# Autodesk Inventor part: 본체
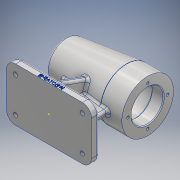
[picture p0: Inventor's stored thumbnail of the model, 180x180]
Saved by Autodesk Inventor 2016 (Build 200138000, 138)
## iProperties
Created: 2018-09
Part Number: 본체
Material: 알루미늄 6061
Document SubType Name: Modeling
Designer: CAMTIC
Density: 2.7 g/cm^3
Appearance: 알루미늄 - 평지
Author: CAMTIC
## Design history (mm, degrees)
sketch "스케치1"
  geometry: L1 (56, 35)-(-56, 35); L2 (-56, 35)-(-56, -35); L3 (-56, -35)-(56, -35); L4 (56, -35)-(56, 35); L5 (56, 35)-(-56, -35); L6 (-56, 35)-(56, -35); 1 further point
  constraints: 12 end point, 2 midpoint, 2 parallel, 1 horizontal, 1 perpendicular
  dimensions: "d0" = 112 distance of L2.end L3.end; "d1" = 70 distance of L1.end L2.end
extrude "돌출1" new body sketch "스케치1" distance "d2" = 10; taper "d3" = 0 deg
sketch "스케치2"
  geometry: L1 (0, 129.6)-(0, -21.6) reference; L2 (-105.225, 0)-(138.871, 0) reference; L3 (-70.354, 74)-(64.903, 74); L4 (-52.27, 98.144)-(28, 108); L5 (28, 108)-(56, 108); L6 (56, 108)-(56, 74); L7 (56, 74)-(-56, 74); L8 (104, 74)-(-56, 74); L9 (24, 74)-(-56, 74); A1 r 80 centre (24, 74) between (-52.27, 98.144) and (-56, 74); 1 further point
  constraints: 14 end point, 2 collinear, 2 horizontal, 2 perpendicular, 2 point on circle, 1 centre point
  dimensions: "d4" = 74 distance between parallel lines of L2 L3; "d5" = 28 distance from line of L4.end L6; "d6" = 34 distance of L5.end L6.end; "d7" = 7 deg angle of L4 L5; "d10" = 56 distance between parallel lines of L1 L6; "d13" = 112 distance of L7.end L6.end; "d14" = 80 radius of A1
revolve "회전1" sketch "스케치2" stored, may be unused: angle "d18" = 90 deg
sketch "스케치3"
  geometry: L1 (-52.27, 98.144)-(28, 108) reference; L2 (56, 40)-(56, 108) reference; L3 (28, 108)-(56, 108) reference; L4 (-52.27, 49.856)-(28, 40) reference; L5 (28, 40)-(56, 40) reference; L6 (0, 129.6)-(0, -21.6) reference; L7 (-78.4, 0)-(78.4, 0) reference; L8 (-85.36, 74)-(107.165, 74); L9 (-50, 74)-(-50, 84.5); L10 (-50, 84.5)-(-47, 84.5); L11 (-47, 84.5)-(-47, 90); L12 (-47, 90)-(-43, 90); L13 (-43, 90)-(-43, 91.5); L14 (-43, 91.5)-(-25, 91.5); L15 (-25, 91.5)-(-25, 95); L16 (-25, 95)-(-13, 95); L17 (-13, 95)-(-13, 98); L18 (-13, 98)-(41, 98); L19 (41, 98)-(41, 95); L20 (41, 95)-(56, 95); L21 (56, 95)-(56, 74); L22 (56, 74)-(-50, 74); A1 r 80 centre (24, 74) between (-52.27, 98.144) and (-52.27, 49.856) reference; 1 further point
  constraints: 30 end point, 13 perpendicular, 2 collinear, 1 horizontal, 1 vertical
  dimensions: "d19" = 74 distance between parallel lines of L7 L8; "d20" = 15 distance of L19.end L20.end; "d21" = 54 distance of L17.end L18.end; "d22" = 12 distance of L15.end L16.end; "d23" = 18 distance of L13.end L14.end; "d24" = 4 distance of L11.end L12.end; "d25" = 3 distance of L9.end L10.end; "d26" = 10.5 distance of L9.start L9.end; "d27" = 16 distance between parallel lines of L22 L12; "d28" = 17.5 distance between parallel lines of L22 L14; "d29" = 21 distance between parallel lines of L22 L16; "d30" = 24 distance between parallel lines of L8 L18; "d31" = 21 distance between parallel lines of L8 L20
revolve "회전2" sketch "스케치3" stored, may be unused: angle "d32" = 90 deg
fillet "모깎기1" dims "d33" = 0.3
fillet "모깎기2" dims "d34" = 3
chamfer "모따기1" distance "d35" = 1; stored, may be unused: second distance "d36" = 2, angle "d37" = 45 deg
fillet "모깎기3" dims "d38" = 3
fillet "모깎기4" dims "d39" = 3
sketch "스케치4"
  geometry: L1 (-50.331, 49.618)-(27.818, 40.022) reference; L2 (-56, 10)-(56, 10) reference; L3 (-50.331, 49.618)-(27.818, 40.022) reference; L4 (28.183, 40)-(56, 40) reference; L5 (0, 129.6)-(0, -21.6) reference; L6 (-78.4, 0)-(78.4, 0) reference; L7 (-38, 10)-(-27.899, 47.699); L8 (-27.899, 47.699)-(38, 47.699); L9 (38, 47.699)-(38, 10); L10 (38, 10)-(-38, 10); L11 (-56, 0)-(-56, 10) reference; L12 (56, 0)-(56, 10) reference; A1 r 3 centre (28.183, 43) between (27.818, 40.022) and (28.183, 40) reference; 1 further point
  constraints: 8 end point, 1 collinear, 1 horizontal, 1 parallel, 1 vertical
  dimensions: "d40" = 18 distance from line of L7.start L11; "d41" = 18 distance from line of L9.end L12; "d42" = 105 deg angle of L2 L7; "d43" = 37.69876 distance between parallel lines of L10 L8
extrude "돌출2" join sketch "스케치4" stored distance "d44" = 8; taper "d45" = 0 deg
sketch "스케치6" dims "d51" = 52
  geometry: C1 r 34 at (0, 0) reference; C2 r 17.5 at (0, 0) reference; 3 further points
  constraints: 1 coincident, 1 vertical alignment, 2 other
hole "구멍1" sketch "스케치6" at (0, 26) diameter "d52" = 3.459; stored, may be unused: countersink angle "d56" = 90 deg, drill point angle "d58" = 118 deg; dims "d53" = 8, "d54" = 4, "d55" = 2, "d57" = 11
fillet "모깎기5" dims "d62" = 12
hole "구멍2" diameter "d65" = 5.5; stored, may be unused: countersink angle "d69" = 90 deg, drill point angle "d71" = 118 deg; dims "d66" = 5.5, "d67" = 9.5, "d68" = 5.4, "d70" = 11, "d107" = 10, "d108" = 10
fillet "모깎기9" dims "d92" = 3
sketch "스케치12"
  geometry: L1 (10, -23)-(10, 23) reference; L2 (7, 35)-(0, 35) reference; L3 (0, -35)-(7, -35) reference; L4 (55.214, 15.543)-(10, 32); L5 (10, 32)-(10, -32); L6 (10, -32)-(55.596, -15.404); C1 r 34 at (74, 0) reference; A1 r 24.382 centre (74, 0) between (55.214, 15.543) and (55.214, -15.543); 5 further points
  constraints: 6 end point, 3 point on line, 2 point on circle, 1 centre point, 1 coincident, 1 collinear, 1 vertical, 4 other
  dimensions: "d93" = 20 deg angle of L4 L2; "d94" = 20 deg angle of L3 L6
extrude "돌출6" join sketch "스케치12" stored distance "d95" = 8; taper "d96" = 0 deg
fillet "모깎기10" dims "d97" = 3
fillet "모깎기11" dims "d98" = 3
fillet "모깎기12" dims "d99" = 3
fillet "모깎기13" dims "d100" = 3
fillet "모깎기14" dims "d101" = 3
fillet "모깎기15" dims "d102" = 3
sketch "스케치13"
  geometry: L1 (26.916, 5.389)-(61.084, 5.389); L2 (61.084, 5.389)-(61.084, 0.611); L3 (61.084, 0.611)-(26.916, 0.611); L4 (26.916, 0.611)-(26.916, 5.389); L5 (44, 5.389)-(44, 0.611); L6 (26.916, 3)-(61.084, 3); L7 (0, 0)-(88, 0) reference; L8 (100, 0)-(100, 7) reference; 1 further point
  constraints: 4 end point, 4 midpoint, 2 other
  dimensions: "d103" = 3 distance between parallel lines of L6 L7; "d104" = 56 distance from line of L5.start L8
feature "엠보싱1" sketch "스케치13" dims "d0" = 112, "d1" = 70, "d105" = 0.5, "d106" = 0
node "솔리드1"
pattern_circular "원형 패턴1" dims angle "d60" = 360 deg
mirror "대칭1"
mirror "대칭2"
